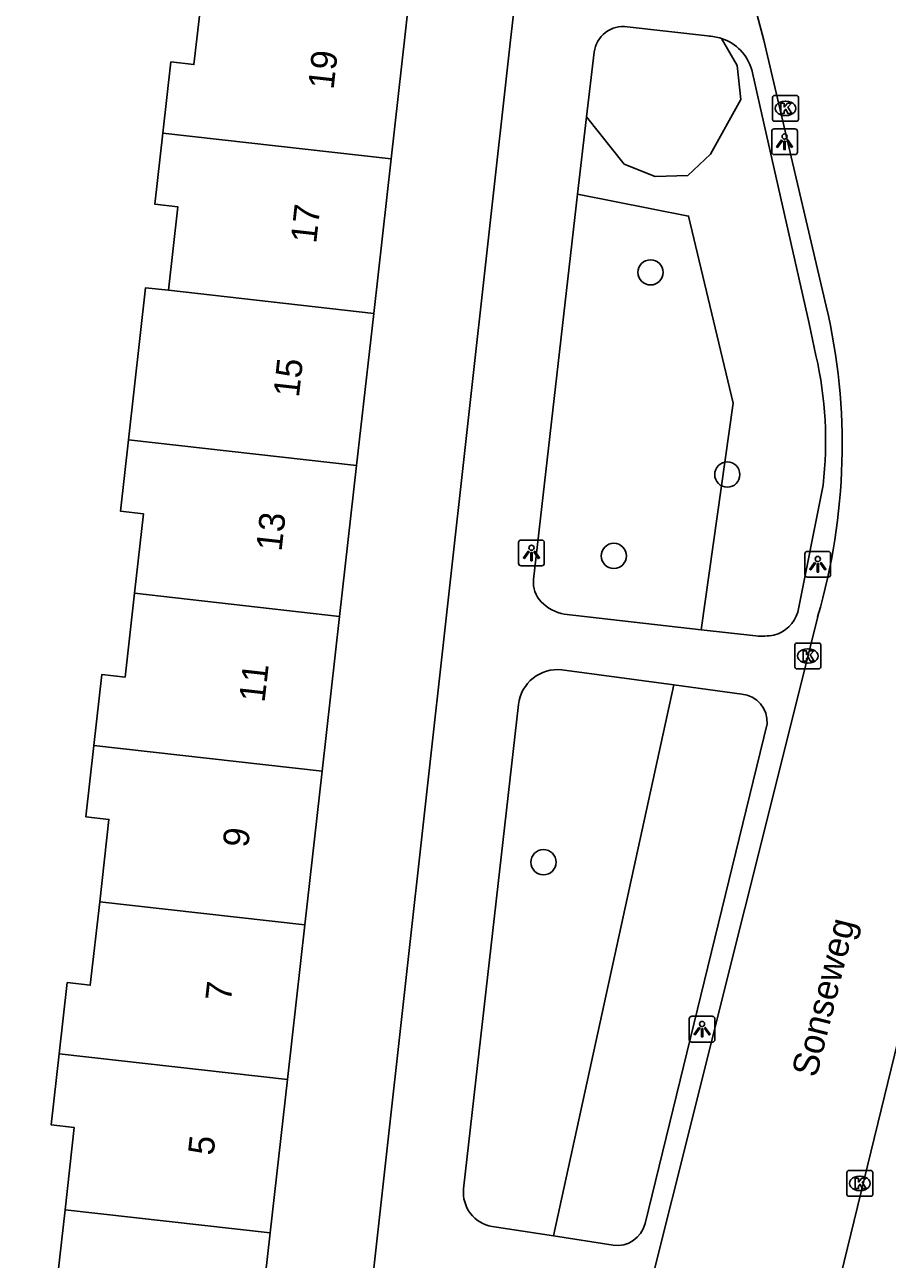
# Model space of a CAD drawing. Extents: x 162026 to 163499, y 387297 to 388169.
# Drawn here: x 162459.51 to 162492.97, y 387650.92 to 387698.78 of the extents above; entities that cross this region are included whole.
import ezdxf

# ---------------------------------------------------------------- set-up
doc = ezdxf.new("R2010")
doc.units = 0
for name, color, linetype in [('IMGEO_Boom', 7, 'Continuous'), ('IMGEO_Groenvoorziening', 7, 'Continuous'), ('IMGEO_Kolk', 7, 'Continuous'), ('IMGEO_Lichtpunt', 7, 'Continuous'), ('IMGEO_Openbare_ruimte_label', 7, 'Continuous'), ('IMGEO_Pand', 7, 'Continuous'), ('IMGEO_Pand_nummerreeks', 7, 'Continuous'), ('IMGEO_Rijbaan_lokaal_open', 7, 'Continuous'), ('IMGEO_Voetpad_open', 7, 'Continuous')]:
    doc.layers.add(name, color=color, linetype=linetype)

msp = doc.modelspace()

# ---------------------------------------------------------------- linework, layer by layer
at = {"layer": 'IMGEO_Boom'}
for centre in [(162483.784, 387689.183), (162486.762, 387681.344), (162482.36, 387678.19), (162479.63, 387666.315)]:
    msp.add_circle(centre, 0.489, dxfattribs=at)
at = {"layer": 'IMGEO_Groenvoorziening'}
for points in [[(162481.306, 387695.213), (162482.766, 387693.375), (162483.966, 387692.906), (162485.226, 387692.936), (162486.104, 387693.77), (162487.29, 387695.879), (162487.144, 387697.197), (162486.535, 387698.254)], [(162480.953, 387692.213), (162485.262, 387691.368), (162486.986, 387684.115), (162485.754, 387675.329)], [(162484.685, 387673.193), (162480.015, 387651.832)]]:
    msp.add_lwpolyline(points, dxfattribs=at)
at = {"layer": 'IMGEO_Kolk'}
for p, q in [((162488.518, 387695.114), (162488.518, 387695.966)), ((162488.593, 387696.04), (162489.445, 387696.04)), ((162489.006, 387695.82), (162489.031, 387695.82)), ((162489.519, 387695.966), (162489.519, 387695.114)), ((162489.029, 387695.26), (162489.004, 387695.26)), ((162489.445, 387695.04), (162488.593, 387695.04)), ((162489.385, 387673.885), (162489.385, 387674.737)), ((162489.46, 387674.811), (162490.312, 387674.811)), ((162489.873, 387674.591), (162489.898, 387674.591)), ((162490.386, 387674.737), (162490.386, 387673.885)), ((162490.312, 387673.811), (162489.46, 387673.811)), ((162489.896, 387674.031), (162489.871, 387674.031)), ((162491.404, 387653.438), (162491.404, 387654.29)), ((162491.479, 387654.364), (162492.331, 387654.364)), ((162491.892, 387654.144), (162491.917, 387654.144)), ((162492.405, 387654.29), (162492.405, 387653.438)), ((162491.915, 387653.584), (162491.89, 387653.584)), ((162492.331, 387653.364), (162491.479, 387653.364))]:
    msp.add_line(p, q, dxfattribs=at)
for points in [[(162488.518, 387695.114), (162488.518, 387695.966)], [(162488.593, 387696.04), (162489.445, 387696.04)], [(162488.839, 387695.74), (162488.962, 387695.74), (162488.962, 387695.589), (162489.092, 387695.74), (162489.256, 387695.74), (162489.11, 387695.589), (162489.263, 387695.34), (162489.111, 387695.34), (162489.026, 387695.504), (162488.962, 387695.437), (162488.962, 387695.34), (162488.839, 387695.34), (162488.839, 387695.74)], [(162489.519, 387695.966), (162489.519, 387695.114)], [(162489.445, 387695.04), (162488.593, 387695.04)], [(162489.385, 387673.885), (162489.385, 387674.737)], [(162489.46, 387674.811), (162490.312, 387674.811)], [(162490.386, 387674.737), (162490.386, 387673.885)], [(162489.706, 387674.511), (162489.829, 387674.511), (162489.829, 387674.36), (162489.959, 387674.511), (162490.123, 387674.511), (162489.977, 387674.36), (162490.13, 387674.111), (162489.978, 387674.111), (162489.893, 387674.275), (162489.829, 387674.208), (162489.829, 387674.111), (162489.706, 387674.111), (162489.706, 387674.511)], [(162490.312, 387673.811), (162489.46, 387673.811)], [(162491.404, 387653.438), (162491.404, 387654.29)], [(162491.479, 387654.364), (162492.331, 387654.364)], [(162491.725, 387654.064), (162491.848, 387654.064), (162491.848, 387653.913), (162491.978, 387654.064), (162492.142, 387654.064), (162491.996, 387653.913), (162492.149, 387653.664), (162491.997, 387653.664), (162491.912, 387653.828), (162491.848, 387653.761), (162491.848, 387653.664), (162491.725, 387653.664), (162491.725, 387654.064)], [(162492.405, 387654.29), (162492.405, 387653.438)], [(162492.331, 387653.364), (162491.479, 387653.364)]]:
    msp.add_lwpolyline(points, dxfattribs=at)
for centre, start, end in [((162488.595, 387695.964), 91.552, 178.448), ((162488.595, 387695.964), 91.552, 178.448), ((162489.443, 387695.964), 1.552, 88.448), ((162489.443, 387695.964), 1.552, 88.448), ((162488.595, 387695.116), 181.552, 268.448), ((162488.595, 387695.116), 181.552, 268.448), ((162489.443, 387695.116), 271.552, 358.448), ((162489.443, 387695.116), 271.552, 358.448), ((162489.462, 387674.735), 91.552, 178.448), ((162489.462, 387674.735), 91.552, 178.448), ((162490.31, 387674.735), 1.552, 88.448), ((162490.31, 387674.735), 1.552, 88.448), ((162489.462, 387673.887), 181.552, 268.448), ((162489.462, 387673.887), 181.552, 268.448), ((162490.31, 387673.887), 271.552, 358.448), ((162490.31, 387673.887), 271.552, 358.448), ((162491.481, 387654.288), 91.552, 178.448), ((162491.481, 387654.288), 91.552, 178.448), ((162492.329, 387654.288), 1.552, 88.448), ((162492.329, 387654.288), 1.552, 88.448), ((162491.481, 387653.44), 181.552, 268.448), ((162491.481, 387653.44), 181.552, 268.448), ((162492.329, 387653.44), 271.552, 358.448), ((162492.329, 387653.44), 271.552, 358.448)]:
    msp.add_arc(centre, 0.0765, start, end, dxfattribs=at)
for centre, major_axis, ratio, start_param, end_param in [((162489.005, 387695.54), (-0.387, 0.002), 0.722429, 4.712389, 7.853982), ((162489.03, 387695.54), (-0.39, 0.002), 0.717154, 1.570796, 4.712389), ((162489.872, 387674.311), (-0.387, 0.002), 0.722429, 4.712389, 7.853982), ((162489.897, 387674.311), (-0.39, 0.002), 0.717154, 1.570796, 4.712389), ((162491.891, 387653.864), (-0.387, 0.002), 0.722429, 4.712389, 7.853982), ((162491.916, 387653.864), (-0.39, 0.002), 0.717154, 1.570796, 4.712389)]:
    msp.add_ellipse(centre, major_axis=major_axis, ratio=ratio, start_param=start_param, end_param=end_param, dxfattribs=at)
at = {"layer": 'IMGEO_Lichtpunt'}
for p, q in [((162489.387, 387694.747), (162488.579, 387694.747)), ((162489.387, 387694.747), (162488.579, 387694.747)), ((162488.485, 387694.652), (162488.485, 387693.845)), ((162488.485, 387694.652), (162488.485, 387693.845)), ((162489.481, 387693.845), (162489.481, 387694.652)), ((162489.481, 387693.845), (162489.481, 387694.652)), ((162488.579, 387693.751), (162489.387, 387693.751)), ((162488.579, 387693.751), (162489.387, 387693.751)), ((162478.667, 387678.71), (162478.667, 387677.903)), ((162478.667, 387678.71), (162478.667, 387677.903)), ((162479.569, 387678.805), (162478.761, 387678.805)), ((162479.569, 387678.805), (162478.761, 387678.805)), ((162479.663, 387677.903), (162479.663, 387678.71)), ((162479.663, 387677.903), (162479.663, 387678.71)), ((162489.773, 387678.272), (162489.773, 387677.465)), ((162489.773, 387678.272), (162489.773, 387677.465)), ((162490.675, 387678.367), (162489.867, 387678.367)), ((162490.675, 387678.367), (162489.867, 387678.367)), ((162490.769, 387677.465), (162490.769, 387678.272)), ((162490.769, 387677.465), (162490.769, 387678.272)), ((162478.761, 387677.809), (162479.569, 387677.809)), ((162478.761, 387677.809), (162479.569, 387677.809)), ((162489.867, 387677.371), (162490.675, 387677.371)), ((162489.867, 387677.371), (162490.675, 387677.371)), ((162485.285, 387660.246), (162485.285, 387659.439)), ((162485.285, 387660.246), (162485.285, 387659.439)), ((162486.187, 387660.341), (162485.379, 387660.341)), ((162486.187, 387660.341), (162485.379, 387660.341)), ((162486.281, 387659.439), (162486.281, 387660.246)), ((162486.281, 387659.439), (162486.281, 387660.246)), ((162485.379, 387659.345), (162486.187, 387659.345)), ((162485.379, 387659.345), (162486.187, 387659.345))]:
    msp.add_line(p, q, dxfattribs=at)
for points in [[(162488.859, 387694.316), (162488.898, 387694.288), (162488.71, 387694.026), (162488.672, 387694.053), (162488.859, 387694.316)], [(162488.961, 387694.268), (162489.008, 387694.268), (162489.008, 387693.946), (162488.961, 387693.946), (162488.961, 387694.268)], [(162489.071, 387694.288), (162489.109, 387694.315), (162489.296, 387694.053), (162489.257, 387694.025), (162489.071, 387694.288)], [(162479.041, 387678.374), (162479.08, 387678.346), (162478.892, 387678.084), (162478.854, 387678.111), (162479.041, 387678.374)], [(162479.143, 387678.326), (162479.19, 387678.326), (162479.19, 387678.004), (162479.143, 387678.004), (162479.143, 387678.326)], [(162479.253, 387678.346), (162479.291, 387678.373), (162479.478, 387678.111), (162479.439, 387678.083), (162479.253, 387678.346)], [(162490.147, 387677.936), (162490.186, 387677.908), (162489.998, 387677.646), (162489.96, 387677.673), (162490.147, 387677.936)], [(162490.359, 387677.908), (162490.397, 387677.935), (162490.584, 387677.673), (162490.545, 387677.645), (162490.359, 387677.908)], [(162490.249, 387677.888), (162490.296, 387677.888), (162490.296, 387677.566), (162490.249, 387677.566), (162490.249, 387677.888)], [(162485.659, 387659.91), (162485.698, 387659.882), (162485.51, 387659.62), (162485.472, 387659.647), (162485.659, 387659.91)], [(162485.761, 387659.862), (162485.808, 387659.862), (162485.808, 387659.54), (162485.761, 387659.54), (162485.761, 387659.862)], [(162485.871, 387659.882), (162485.909, 387659.909), (162486.096, 387659.647), (162486.057, 387659.619), (162485.871, 387659.882)]]:
    msp.add_lwpolyline(points, dxfattribs=at)
for centre in [(162488.984, 387694.45), (162479.166, 387678.508), (162490.272, 387678.07), (162485.784, 387660.044)]:
    msp.add_circle(centre, 0.0994, dxfattribs=at)
for centre, start, end in [((162488.579, 387694.652), 90, 180), ((162488.579, 387694.652), 90, 180), ((162489.387, 387694.652), 0, 90), ((162489.387, 387694.652), 0, 90), ((162488.579, 387693.845), 180, 270), ((162488.579, 387693.845), 180, 270), ((162489.387, 387693.845), 270, 0), ((162489.387, 387693.845), 270, 360), ((162478.761, 387678.71), 90, 180), ((162478.761, 387678.71), 90, 180), ((162479.569, 387678.71), 0, 90), ((162479.569, 387678.71), 0, 90), ((162489.867, 387678.272), 90, 180), ((162489.867, 387678.272), 90, 180), ((162490.675, 387678.272), 0, 90), ((162490.675, 387678.272), 0, 90), ((162478.761, 387677.903), 180, 270), ((162478.761, 387677.903), 180, 270), ((162479.569, 387677.903), 270, 0), ((162479.569, 387677.903), 270, 360), ((162489.867, 387677.465), 180, 270), ((162489.867, 387677.465), 180, 270), ((162490.675, 387677.465), 270, 0), ((162490.675, 387677.465), 270, 360), ((162485.379, 387660.246), 90, 180), ((162485.379, 387660.246), 90, 180), ((162486.187, 387660.246), 0, 90), ((162486.187, 387660.246), 0, 90), ((162485.379, 387659.439), 180, 270), ((162485.379, 387659.439), 180, 270), ((162486.187, 387659.439), 270, 0), ((162486.187, 387659.439), 270, 360)]:
    msp.add_arc(centre, 0.0946, start, end, dxfattribs=at)
at = {"layer": 'IMGEO_Pand'}
for points in [[(162464.869, 387694.582), (162465.18, 387697.341), (162466.074, 387697.24), (162466.45, 387700.58), (162469.441, 387700.243), (162474.409, 387699.683), (162473.722, 387693.585)], [(162465.088, 387688.488), (162465.452, 387691.722), (162464.558, 387691.823), (162464.869, 387694.582)], [(162473.722, 387693.585), (162464.869, 387694.582)], [(162473.722, 387693.585), (162473.047, 387687.592)], [(162465.088, 387688.488), (162464.194, 387688.589), (162463.529, 387682.687)], [(162473.047, 387687.592), (162465.088, 387688.488)], [(162472.382, 387681.69), (162473.047, 387687.592)], [(162463.764, 387676.741), (162464.112, 387679.827), (162463.218, 387679.928), (162463.529, 387682.687)], [(162463.529, 387682.687), (162472.382, 387681.69)], [(162472.382, 387681.69), (162471.723, 387675.844)], [(162462.193, 387670.836), (162462.504, 387673.595), (162463.398, 387673.494), (162463.764, 387676.741)], [(162463.764, 387676.741), (162471.723, 387675.844)], [(162471.723, 387675.844), (162471.046, 387669.839)], [(162462.417, 387664.785), (162462.776, 387667.976), (162461.882, 387668.077), (162462.193, 387670.836)], [(162462.193, 387670.836), (162471.046, 387669.839)], [(162471.046, 387669.839), (162470.376, 387663.889)], [(162460.847, 387658.889), (162461.158, 387661.648), (162462.052, 387661.547), (162462.417, 387664.785)], [(162470.376, 387663.889), (162462.417, 387664.785)], [(162470.376, 387663.889), (162469.7, 387657.892)], [(162461.071, 387652.841), (162461.43, 387656.029), (162460.536, 387656.13), (162460.847, 387658.889)], [(162460.847, 387658.889), (162469.7, 387657.892)], [(162469.7, 387657.892), (162469.03, 387651.945)], [(162459.506, 387646.989), (162459.817, 387649.748), (162460.711, 387649.647), (162461.071, 387652.841)], [(162469.03, 387651.945), (162461.071, 387652.841)], [(162469.03, 387651.945), (162468.359, 387645.992)]]:
    msp.add_lwpolyline(points, dxfattribs=at)
at = {"layer": 'IMGEO_Rijbaan_lokaal_open'}
for points in [[(162490.602, 387687.877), (162488.177, 387698.19), (162486.539, 387704.356), (162486.11, 387705.881)], [(162486.172, 387630.015), (162486.508, 387631.255), (162487.791, 387636.482), (162497.263, 387675.316), (162498.286, 387679.137), (162498.305, 387679.17), (162498.449, 387679.931), (162498.615, 387681.926), (162498.638, 387684.945)], [(162478.964, 387630.648), (162490.267, 387675.831)]]:
    msp.add_lwpolyline(points, dxfattribs=at)
msp.add_arc((162467.417, 387682.494), 23.801, 343.743, 13.071, dxfattribs=at)
at = {"layer": 'IMGEO_Voetpad_open'}
for points in [[(162471.82, 387639.553), (162478.34, 387698.075), (162483.821, 387745.82)], [(162482.88, 387698.703), (162485.989, 387698.352)], [(162481.306, 387695.213), (162481.601, 387697.723)], [(162487.707, 387697.035), (162488.021, 387695.657), (162489.943, 387687.203), (162490.199, 387685.954)], [(162480.953, 387692.213), (162481.306, 387695.213)], [(162479.249, 387677.274), (162480.953, 387692.213)], [(162490.475, 387680.93), (162489.496, 387676.007)], [(162485.754, 387675.329), (162480.436, 387675.932)], [(162487.867, 387675.09), (162485.754, 387675.329)], [(162480.348, 387673.775), (162484.685, 387673.193)], [(162484.685, 387673.193), (162487.322, 387672.835)], [(162476.532, 387653.657), (162478.662, 387672.431)], [(162488.31, 387671.677), (162483.572, 387652.305)], [(162480.015, 387651.832), (162477.646, 387652.197)], [(162482.329, 387651.474), (162480.015, 387651.832)]]:
    msp.add_lwpolyline(points, dxfattribs=at)
for centre, radius, start, end in [((162482.717, 387697.592), 1.123, 81.6353, 173.2851), ((162485.527, 387694.207), 4.171, 76.0118, 83.6372), ((162485.977, 387696.545), 1.798, 15.8266, 71.9212), ((162475.953, 387682.652), 14.624, 353.2385, 13.0504), ((162480.279, 387677.143), 1.038, 172.7608, 225.0207), ((162480.772, 387677.63), 1.731, 224.8641, 258.8108), ((162488.262, 387676.372), 1.286, 283.9313, 343.5339), ((162488.103, 387677.606), 2.527, 264.6516, 280.7084), ((162480.178, 387672.259), 1.525, 83.593, 173.5274), ((162487.21, 387671.739), 1.102, 356.7947, 84.1466), ((162477.849, 387653.507), 1.325, 173.4922, 261.1961), ((162482.497, 387652.568), 1.107, 261.2911, 346.2378)]:
    msp.add_arc(centre, radius, start, end, dxfattribs=at)

# ---------------------------------------------------------------- texts
at = {"layer": 'IMGEO_Openbare_ruimte_label'}
msp.add_text('Sonseweg', height=1, rotation=75.9916, dxfattribs=at).set_placement((162490.217, 387657.936))
at = {"layer": 'IMGEO_Pand_nummerreeks'}
for s, rotation, p in [('19', 83.5712, (162471.486, 387696.25)), ('17', 83.5712, (162470.813, 387690.281)), ('15', 83.5716, (162470.141, 387684.311)), ('13', 83.5712, (162469.468, 387678.342)), ('11', 83.5712, (162468.809, 387672.486)), ('9', 83.5712, (162468.175, 387666.86)), ('7', 83.5712, (162467.502, 387660.89)), ('5', 83.5712, (162466.83, 387654.921))]:
    msp.add_text(s, height=1, rotation=rotation, dxfattribs=at).set_placement(p)

doc.saveas('drawing.dxf')
